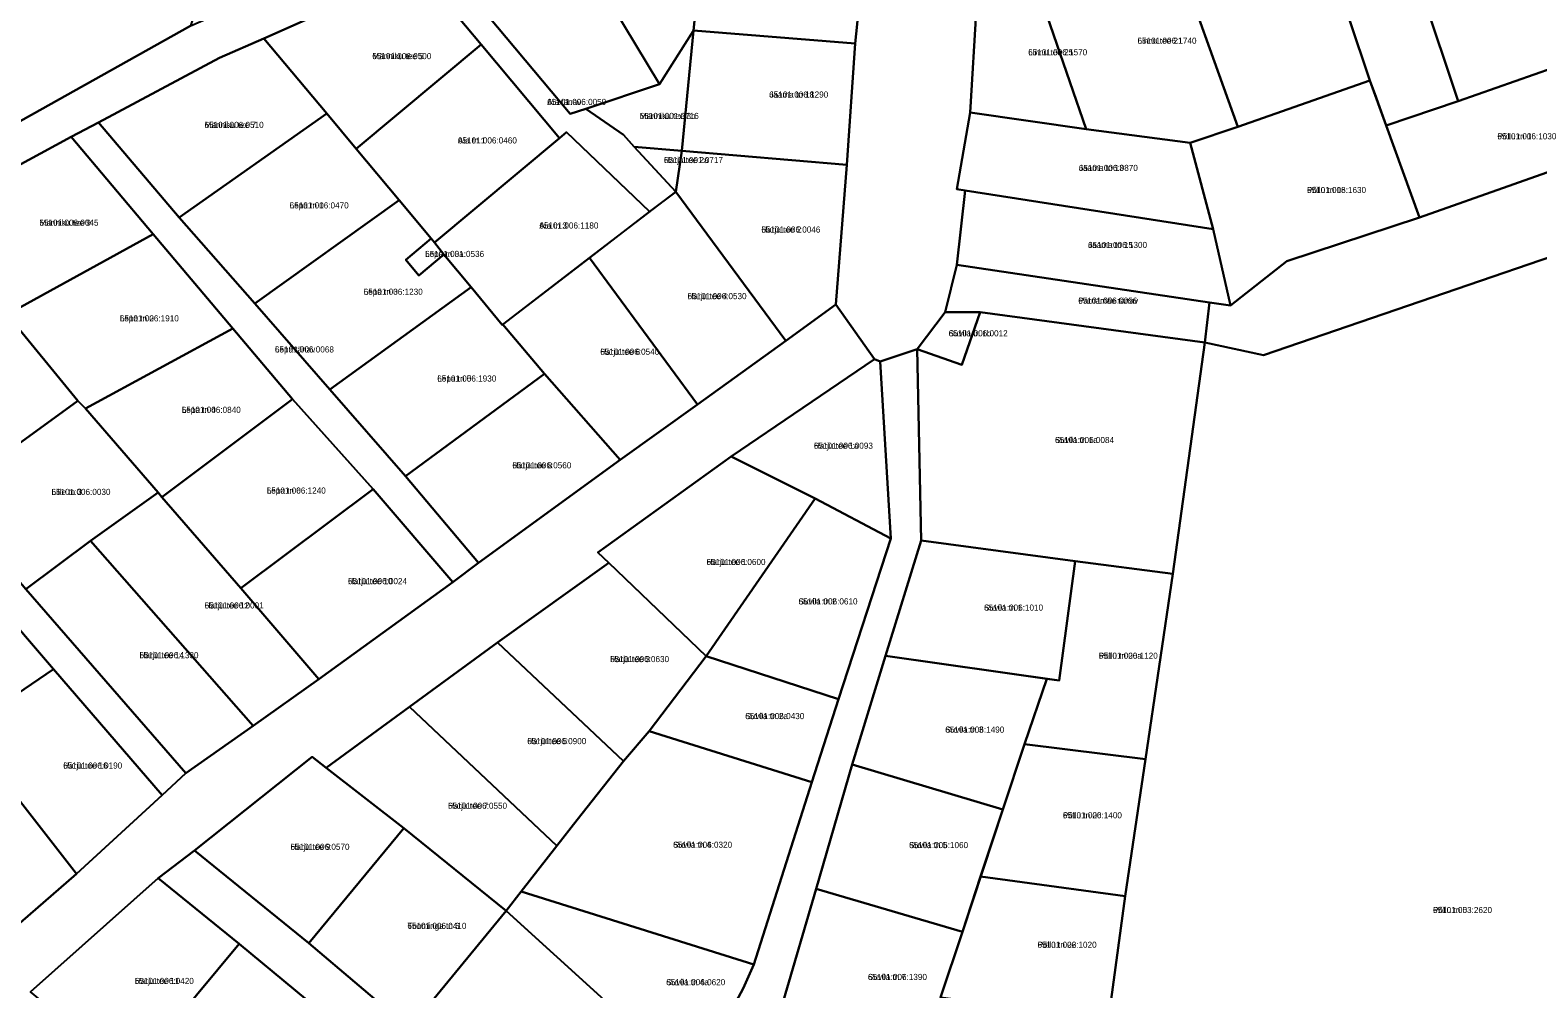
# Model space of a CAD drawing. Extents: x 556044 to 574504, y 6567077 to 6586269.
# Drawn here: x 560853.5 to 561223.9, y 6581131.9 to 6581367.4 of the extents above; entities that cross this region are included whole.
import ezdxf

# ---------------------------------------------------------------- set-up
doc = ezdxf.new("R2010")
doc.units = 0
for name, color, linetype in [('L_AADRESS', 7, 'Continuous'), ('PIIR', 7, 'Continuous'), ('TUNNUS', 7, 'Continuous')]:
    doc.layers.add(name, color=color, linetype=linetype)

msp = doc.modelspace()

# ---------------------------------------------------------------- linework, layer by layer
at = {"layer": 'PIIR'}
for points in [[(560773.9, 6581423.09), (560847.24, 6581470.37), (560849.63, 6581466.49), (560870.05, 6581433.46), (560861.24, 6581427.52), (560876.14, 6581401.42), (560894.86, 6581374.38), (560892.91, 6581368.46), (560827.74, 6581332.04), (560800.22, 6581378.97)], [(561156.54, 6581287.57), (561142.08, 6581290.69), (561143.25, 6581300.49), (561148.41, 6581299.73), (561162.27, 6581310.63), (561194.83, 6581321.35), (561241.19, 6581337.71), (561241.29, 6581337.45), (561244.33, 6581329.07), (561273.25, 6581339.37), (561280.48, 6581341.95), (561277.04, 6581350.09), (561311.86, 6581362.68), (561348.98, 6581375.76), (561390.15, 6581389.72), (561405.51, 6581395.29), (561433.73, 6581404.99), (561462.09, 6581414.77), (561491.94, 6581428.14), (561491.73, 6581420.63), (561289.22, 6581333.22), (561277.91, 6581329.15)], [(561021.3, 6581415.28), (561019.46, 6581396.6), (561016.51, 6581367.31), (561008.13, 6581354.12), (560982.09, 6581397.36)], [(561210.87, 6581416.48), (561229.26, 6581367.46), (561232.35, 6581359.79), (561204.33, 6581349.93), (561202.03, 6581356.84), (561185.2, 6581407.17)], [(561185.2, 6581407.17), (561202.03, 6581356.84), (561204.33, 6581349.93), (561186.63, 6581343.99), (561182.64, 6581355), (561167.24, 6581401.05)], [(561167.24, 6581401.05), (561182.64, 6581355), (561150.19, 6581343.67), (561133.76, 6581389.56)], [(560982.09, 6581397.36), (561008.13, 6581354.12), (560990.06, 6581348.08), (560986.17, 6581346.8), (560954.75, 6581384.44)], [(561056.18, 6581364.1), (561016.51, 6581367.31), (561019.46, 6581396.6), (561059.19, 6581392.76)], [(561100.94, 6581378.06), (561133.76, 6581389.56), (561150.19, 6581343.67), (561138.46, 6581339.69), (561112.96, 6581343.09)], [(560954.75, 6581384.44), (560986.17, 6581346.8), (560990.06, 6581348.08), (560999.33, 6581341.63), (561001.88, 6581338.76), (561012.18, 6581327.69), (561005.72, 6581322.81), (560985.29, 6581342.33), (560983.58, 6581340.88), (560964.33, 6581363.89), (560948.94, 6581382.29)], [(560910.91, 6581365.37), (560948.94, 6581382.29), (560964.33, 6581363.89), (560933.64, 6581338.23), (560926.38, 6581346.92)], [(561100.94, 6581378.06), (561112.96, 6581343.09), (561084.47, 6581347.13), (561086.01, 6581373.05)], [(560999.33, 6581341.63), (560990.06, 6581348.08), (561008.13, 6581354.12), (561016.51, 6581367.31), (561013.62, 6581337.74), (561001.88, 6581338.76)], [(561054.15, 6581334.32), (561013.62, 6581337.74), (561016.51, 6581367.31), (561056.18, 6581364.1)], [(560900.02, 6581360.61), (560910.91, 6581365.37), (560926.38, 6581346.92), (560890.17, 6581321.37), (560870.36, 6581344.66)], [(560983.58, 6581340.88), (560952.89, 6581315.22), (560952.07, 6581316.2), (560944.16, 6581325.66), (560933.64, 6581338.23), (560964.33, 6581363.89)], [(561186.63, 6581343.99), (561204.33, 6581349.93), (561232.35, 6581359.79), (561241.19, 6581337.71), (561194.83, 6581321.35)], [(561144.15, 6581318.47), (561138.46, 6581339.69), (561150.19, 6581343.67), (561182.64, 6581355), (561184.17, 6581350.82), (561186.63, 6581343.99), (561194.83, 6581321.35), (561162.27, 6581310.63), (561148.41, 6581299.73)], [(560870.36, 6581344.66), (560890.17, 6581321.37), (560908.7, 6581300.26), (560927.18, 6581279.11), (560945.76, 6581257.85), (560963.69, 6581236.5), (560957.37, 6581231.79), (560937.81, 6581254.65), (560918.01, 6581276.72), (560903.3, 6581294.07), (560883.76, 6581317.25), (560863.64, 6581341.17)], [(560926.38, 6581346.92), (560933.64, 6581338.23), (560944.16, 6581325.66), (560908.7, 6581300.26), (560890.17, 6581321.37)], [(561144.15, 6581318.47), (561083.26, 6581328), (561081.21, 6581328.32), (561084.47, 6581347.13), (561112.96, 6581343.09), (561138.46, 6581339.69)], [(560863.64, 6581341.17), (560883.76, 6581317.25), (560847.93, 6581297.53), (560828.65, 6581320.56), (560827.71, 6581321.69)], [(560985.29, 6581342.33), (561005.72, 6581322.81), (560990.91, 6581311.49), (560969.5, 6581294.96), (560961.9, 6581304.27), (560955.18, 6581312.29), (560952.89, 6581315.22), (560983.58, 6581340.88)], [(561012.18, 6581327.69), (561001.88, 6581338.76), (561013.62, 6581337.74)], [(561013.62, 6581337.74), (561054.15, 6581334.32), (561051.48, 6581299.96), (561039.16, 6581291.09), (561012.18, 6581327.69)], [(561156.54, 6581287.57), (561277.91, 6581329.15), (561273.57, 6581201.64), (561262.39, 6581044.27), (561258.56, 6580995.78), (561234.98, 6580997.08), (561193.46, 6580999.44), (561156.06, 6581001.74), (561152.61, 6581001.98), (561153.08, 6581010.42), (561148.47, 6581015.32), (561151.48, 6581067.66), (561152.22, 6581086.94), (561151.1, 6581119.14), (561126.27, 6581123.17), (561118.4, 6581124.45), (561122.49, 6581154.68), (561127.51, 6581188.31), (561134.24, 6581233.82), (561142.08, 6581290.69)], [(560944.16, 6581325.66), (560952.07, 6581316.2), (560945.83, 6581310.96), (560949.06, 6581307.15), (560955.18, 6581312.29), (560961.9, 6581304.27), (560927.18, 6581279.11), (560908.7, 6581300.26)], [(561012.18, 6581327.69), (561039.16, 6581291.09), (561017.49, 6581275.45), (560990.91, 6581311.49)], [(561083.26, 6581328), (561144.15, 6581318.47), (561148.41, 6581299.73), (561143.25, 6581300.49), (561081.15, 6581309.7)], [(560883.76, 6581317.25), (560903.3, 6581294.07), (560867.12, 6581274.42), (560865.26, 6581276.36), (560847.93, 6581297.53)], [(560952.89, 6581315.22), (560955.18, 6581312.29), (560949.06, 6581307.15), (560945.83, 6581310.96), (560952.07, 6581316.2)], [(560990.91, 6581311.49), (561017.49, 6581275.45), (560998.48, 6581261.8), (560979.85, 6581282.99), (560969.66, 6581295.09)], [(561081.15, 6581309.7), (561143.25, 6581300.49), (561142.08, 6581290.69), (561086.92, 6581298.1), (561078.28, 6581298.07)], [(560927.18, 6581279.11), (560961.9, 6581304.27), (560969.5, 6581294.96), (560969.66, 6581295.09), (560979.85, 6581282.99), (560945.76, 6581257.85)], [(560785.01, 6581296.7), (560792.53, 6581300.86), (560812.1, 6581278.05), (560832.97, 6581252.91), (560852.48, 6581230.07), (560891.75, 6581184.87), (560886.01, 6581179.5), (560859.27, 6581210.42), (560844.51, 6581227.52), (560829.56, 6581244.11), (560815.03, 6581261.78)], [(560812.1, 6581278.05), (560847.93, 6581297.53), (560865.26, 6581276.36), (560832.97, 6581252.91)], [(561086.92, 6581298.1), (561082.43, 6581285.15), (561071.42, 6581289.01), (561078.28, 6581298.07)], [(561071.42, 6581289.01), (561082.43, 6581285.15), (561086.92, 6581298.1), (561142.08, 6581290.69), (561134.24, 6581233.82), (561110.25, 6581236.97), (561072.45, 6581241.98)], [(560885.88, 6581252.7), (560884.95, 6581253.77), (560867.12, 6581274.42), (560903.3, 6581294.07), (560918.01, 6581276.72)], [(561025.72, 6581262.66), (561060.94, 6581286.6), (561062.33, 6581286.03), (561064.93, 6581242.51), (561046.41, 6581252.33)], [(560979.85, 6581282.99), (560998.48, 6581261.8), (560963.69, 6581236.5), (560945.76, 6581257.85)], [(560832.97, 6581252.91), (560865.26, 6581276.36), (560867.12, 6581274.42), (560884.95, 6581253.77), (560868.38, 6581241.96), (560852.48, 6581230.07)], [(560885.88, 6581252.7), (560918.01, 6581276.72), (560937.81, 6581254.65), (560905.31, 6581230.35)], [(561019.64, 6581213.6), (560995.69, 6581236.5), (560992.98, 6581239.05), (561025.72, 6581262.66), (561046.41, 6581252.33)], [(560884.95, 6581253.77), (560885.88, 6581252.7), (560905.31, 6581230.35), (560924.43, 6581207.92), (560908.32, 6581196.48), (560868.38, 6581241.96)], [(560924.43, 6581207.92), (560905.31, 6581230.35), (560937.81, 6581254.65), (560957.37, 6581231.79)], [(561052.15, 6581203.05), (561019.64, 6581213.6), (561046.41, 6581252.33), (561064.93, 6581242.51)], [(560891.75, 6581184.87), (560852.48, 6581230.07), (560868.38, 6581241.96), (560908.32, 6581196.48)], [(561063.69, 6581213.69), (561072.45, 6581241.98), (561110.25, 6581236.97), (561106.31, 6581207.61)], [(561005.64, 6581195.22), (560999.29, 6581187.78), (560968.32, 6581217), (560995.69, 6581236.5), (561019.64, 6581213.6)], [(561134.24, 6581233.82), (561127.51, 6581188.31), (561097.83, 6581192), (561103.26, 6581208.02), (561106.31, 6581207.61), (561110.25, 6581236.97)], [(560786.54, 6581187.88), (560844.51, 6581227.52), (560859.27, 6581210.42), (560837.32, 6581195.51), (560801, 6581170.84)], [(560968.32, 6581217), (560999.29, 6581187.78), (560987.95, 6581173.43), (560982.89, 6581166.99), (560946.76, 6581201.2)], [(560886.01, 6581179.5), (560864.96, 6581160.11), (560837.32, 6581195.51), (560859.27, 6581210.42)], [(561045.54, 6581182.67), (561005.64, 6581195.22), (561019.64, 6581213.6), (561052.15, 6581203.05)], [(561063.69, 6581213.69), (561103.26, 6581208.02), (561097.83, 6581192), (561092.47, 6581175.95), (561055.48, 6581186.99)], [(560946.76, 6581201.2), (560982.89, 6581166.99), (560974.19, 6581155.82), (560970.46, 6581151.05), (560945.33, 6581171.32), (560926.23, 6581186.2)], [(560801, 6581170.84), (560837.32, 6581195.51), (560864.96, 6581160.11), (560833.4, 6581132.76)], [(561031.31, 6581137.85), (560974.19, 6581155.82), (560982.89, 6581166.99), (560987.95, 6581173.43), (560999.29, 6581187.78), (561005.64, 6581195.22), (561045.54, 6581182.67)], [(561086.96, 6581159.46), (561092.47, 6581175.95), (561097.83, 6581192), (561127.51, 6581188.31), (561122.49, 6581154.68)], [(560922.84, 6581188.91), (560926.23, 6581186.2), (560945.33, 6581171.32), (560921.97, 6581143.12), (560893.93, 6581165.9)], [(561055.48, 6581186.99), (561092.47, 6581175.95), (561082.59, 6581145.91), (561046.66, 6581156.43)], [(560921.97, 6581143.12), (560945.33, 6581171.32), (560970.46, 6581151.05), (560946.74, 6581122.16)], [(560893.93, 6581165.9), (560921.97, 6581143.12), (560946.74, 6581122.16), (560971.5, 6581101.14), (560999.77, 6581077.84), (560995.15, 6581067.99), (560976.49, 6581083.5), (560954.54, 6581101.74), (560932.54, 6581120.02), (560904.9, 6581142.98), (560884.95, 6581159.1)], [(560904.9, 6581142.98), (560878.24, 6581110.94), (560853.59, 6581131.14), (560884.95, 6581159.1)], [(561118.4, 6581124.45), (561077.18, 6581129.76), (561082.59, 6581145.91), (561086.96, 6581159.46), (561122.49, 6581154.68)], [(561028.7, 6581131.98), (561016.7, 6581109.74), (560994.61, 6581129.07), (560970.46, 6581151.05), (560974.19, 6581155.82), (561031.31, 6581137.85)], [(561046.66, 6581156.43), (561082.59, 6581145.91), (561077.18, 6581129.76), (561071.58, 6581111.69), (561066.28, 6581114.51), (561038.5, 6581128.75)], [(560946.74, 6581122.16), (560970.46, 6581151.05), (560994.61, 6581129.07), (560971.5, 6581101.14)], [(560882.71, 6581107.19), (560878.24, 6581110.94), (560904.9, 6581142.98), (560932.54, 6581120.02), (560905.79, 6581087.86)]]:
    msp.add_lwpolyline(points, close=True, dxfattribs=at)
for points in [[(560827.74, 6581332.04), (560892.91, 6581368.46), (560907.23, 6581374.7), (560933.6, 6581386.02), (560979.42, 6581406.72), (560986.67, 6581411.52), (561026.11, 6581428.47), (561054.34, 6581440.77), (561061.33, 6581444.69), (561063.17, 6581433.71), (561021.3, 6581415.28), (560982.09, 6581397.36), (560954.75, 6581384.44), (560948.94, 6581382.29), (560910.91, 6581365.37), (560900.02, 6581360.61), (560870.36, 6581344.66), (560863.64, 6581341.17), (560827.71, 6581321.69)], [(561086.01, 6581373.05), (561084.47, 6581347.13), (561081.21, 6581328.32), (561083.26, 6581328), (561081.15, 6581309.7), (561078.28, 6581298.07), (561071.42, 6581289.01), (561062.33, 6581286.03), (561060.94, 6581286.6), (561051.48, 6581299.96), (561054.15, 6581334.32), (561056.18, 6581364.1), (561059.19, 6581392.76)], [(560728.91, 6581027.1), (560833.4, 6581132.76), (560864.96, 6581160.11), (560886.01, 6581179.5), (560891.75, 6581184.87), (560908.32, 6581196.48), (560924.43, 6581207.92), (560957.37, 6581231.79), (560963.69, 6581236.5), (560998.48, 6581261.8), (561017.49, 6581275.45), (561039.16, 6581291.09), (561051.48, 6581299.96), (561060.94, 6581286.6), (561025.72, 6581262.66), (560992.98, 6581239.05), (560995.69, 6581236.5), (560968.32, 6581217), (560946.76, 6581201.2), (560926.23, 6581186.2), (560922.84, 6581188.91), (560893.93, 6581165.9), (560884.95, 6581159.1), (560853.59, 6581131.14)], [(561016.7, 6581109.74), (561028.7, 6581131.98), (561031.31, 6581137.85), (561045.54, 6581182.67), (561052.15, 6581203.05), (561064.93, 6581242.51), (561062.33, 6581286.03), (561071.42, 6581289.01), (561072.45, 6581241.98), (561063.69, 6581213.69), (561055.48, 6581186.99), (561046.66, 6581156.43), (561038.5, 6581128.75)]]:
    msp.add_lwpolyline(points, dxfattribs=at)

# ---------------------------------------------------------------- texts
at = {"layer": 'L_AADRESS'}
for s, p in [('Linnu tee 25', (561098.71, 6581361.21)), ('Linnu tee 21', (561125.56, 6581364.05)), ('Männiku tee 5', (560937.59, 6581360.26)), ('Jaama tn 18', (561035.09, 6581350.82)), ('Aia tänav', (560980.56, 6581349.01)), ('Männiku tee 7', (560896.4, 6581343.37)), ('Männiku tee 3b', (561003.29, 6581345.57)), ('Aia tn 1', (560958.61, 6581339.55)), ('Põllu tn 16', (561213.96, 6581340.57)), ('Harju tee 2a', (561009.23, 6581334.73)), ('Jaama tn 13', (561111.15, 6581332.8)), ('Põllu tn 18', (561167.21, 6581327.37)), ('Lepa tn 1', (560917.29, 6581323.59)), ('Männiku tee 9', (560855.83, 6581319.35)), ('Aia tn 3', (560978.63, 6581318.65)), ('Harju tee 2', (561033.16, 6581317.66)), ('Jaama tn 15', (561113.41, 6581313.87)), ('Lepa tn 3a', (560950.56, 6581311.67)), ('Lepa tn 3', (560935.48, 6581302.38)), ('Harju tee 4', (561015.03, 6581301.3)), ('Pärnamäe tänav', (561111.01, 6581300.2)), ('Lepa tn 2', (560875.56, 6581295.84)), ('Suvila tn 1b', (561079.17, 6581292.18)), ('Lepa tänav', (560913.66, 6581288.21)), ('Harju tee 6', (560993.57, 6581287.63)), ('Lepa tn 5', (560953.55, 6581281.06)), ('Lepa tn 4', (560890.78, 6581273.38)), ('Harju tee 1a', (561046.06, 6581264.56)), ('Suvila tn 1a', (561105.3, 6581265.96)), ('Harju tee 8', (560971.99, 6581259.74)), ('Lille tn 3', (560858.78, 6581253.21)), ('Lepa tn 6', (560911.66, 6581253.54)), ('Harju tee 1', (561019.69, 6581236)), ('Harju tee 10', (560931.62, 6581231.29)), ('Harju tee 12', (560896.41, 6581225.32)), ('Suvila tn 2', (561042.29, 6581226.31)), ('Suvila tn 1', (561087.87, 6581224.79)), ('Harju tee 14', (560880.4, 6581213.1)), ('Põllu tn 20a', (561116.04, 6581212.97)), ('Harju tee 3', (560996, 6581212.14)), ('Suvila tn 2a', (561029.21, 6581198.14)), ('Suvila tn 3', (561078.34, 6581194.82)), ('Harju tee 5', (560975.65, 6581191.99)), ('Harju tee 16', (560861.66, 6581185.99)), ('Harju tee 7', (560956.2, 6581176.12)), ('Põllu tn 20', (561107.23, 6581173.78)), ('Harju tee 9', (560917.5, 6581166.02)), ('Suvila tn 4', (561011.48, 6581166.54)), ('Suvila tn 5', (561069.45, 6581166.45)), ('Põllu tn 5', (561198.15, 6581150.5)), ('Toominga tn 6', (560946.21, 6581146.61)), ('Põllu tn 22', (561101.02, 6581141.96)), ('Harju tee 11', (560879.25, 6581133.08)), ('Suvila tn 4a', (561009.79, 6581132.78)), ('Suvila tn 7', (561059.34, 6581134.06))]:
    msp.add_text(s, height=1.5, dxfattribs=at).set_placement(p)
at = {"layer": 'TUNNUS'}
for s, p in [('65101:006:1570', (561098.71, 6581361.21)), ('65101:006:1740', (561125.56, 6581364.05)), ('65101:006:0500', (560937.59, 6581360.26)), ('65101:006:1290', (561035.09, 6581350.82)), ('65101:006:0059', (560980.56, 6581349.01)), ('65101:006:0510', (560896.4, 6581343.37)), ('65101:001:0716', (561003.29, 6581345.57)), ('65101:006:0460', (560958.61, 6581339.55)), ('65101:006:1030', (561213.96, 6581340.57)), ('65101:001:0717', (561009.23, 6581334.73)), ('65101:006:0870', (561111.15, 6581332.8)), ('65101:006:1630', (561167.21, 6581327.37)), ('65101:006:0470', (560917.29, 6581323.59)), ('65101:006:0045', (560855.83, 6581319.35)), ('65101:006:1180', (560978.63, 6581318.65)), ('65101:006:0046', (561033.16, 6581317.66)), ('65101:006:1300', (561113.41, 6581313.87)), ('65101:001:0536', (560950.56, 6581311.67)), ('65101:006:1230', (560935.48, 6581302.38)), ('65101:006:0530', (561015.03, 6581301.3)), ('65101:006:0056', (561111.01, 6581300.2)), ('65101:006:1910', (560875.56, 6581295.84)), ('65101:006:0012', (561079.17, 6581292.18)), ('65101:006:0068', (560913.66, 6581288.21)), ('65101:006:0540', (560993.57, 6581287.63)), ('65101:006:1930', (560953.55, 6581281.06)), ('65101:006:0840', (560890.78, 6581273.38)), ('65101:006:0093', (561046.06, 6581264.56)), ('65101:006:0084', (561105.3, 6581265.96)), ('65101:006:0560', (560971.99, 6581259.74)), ('65101:006:0030', (560858.78, 6581253.21)), ('65101:006:1240', (560911.66, 6581253.54)), ('65101:006:0600', (561019.69, 6581236)), ('65101:006:0024', (560931.62, 6581231.29)), ('65101:006:0001', (560896.41, 6581225.32)), ('65101:006:0610', (561042.29, 6581226.31)), ('65101:006:1010', (561087.87, 6581224.79)), ('65101:006:1330', (560880.4, 6581213.1)), ('65101:006:1120', (561116.04, 6581212.97)), ('65101:006:0630', (560996, 6581212.14)), ('65101:006:0430', (561029.21, 6581198.14)), ('65101:006:1490', (561078.34, 6581194.82)), ('65101:006:0900', (560975.65, 6581191.99)), ('65101:006:0190', (560861.66, 6581185.99)), ('65101:006:0550', (560956.2, 6581176.12)), ('65101:006:1400', (561107.23, 6581173.78)), ('65101:006:0570', (560917.5, 6581166.02)), ('65101:006:0320', (561011.48, 6581166.54)), ('65101:006:1060', (561069.45, 6581166.45)), ('65101:003:2620', (561198.15, 6581150.5)), ('65101:006:0410', (560946.21, 6581146.61)), ('65101:006:1020', (561101.02, 6581141.96)), ('65101:006:0420', (560879.25, 6581133.08)), ('65101:006:0620', (561009.79, 6581132.78)), ('65101:006:1390', (561059.34, 6581134.06))]:
    msp.add_text(s, height=1.5, dxfattribs=at).set_placement(p)

doc.saveas('drawing.dxf')
